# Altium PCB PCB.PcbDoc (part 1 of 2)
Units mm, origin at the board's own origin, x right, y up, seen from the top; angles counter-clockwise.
Board outline 43.18 x 17.78 mm, 4 copper layers (TOP, GND, SIG, BOTTOM), stack 1.586 mm thick; 72 components, 65 nets, 299 pads, 183 vias.
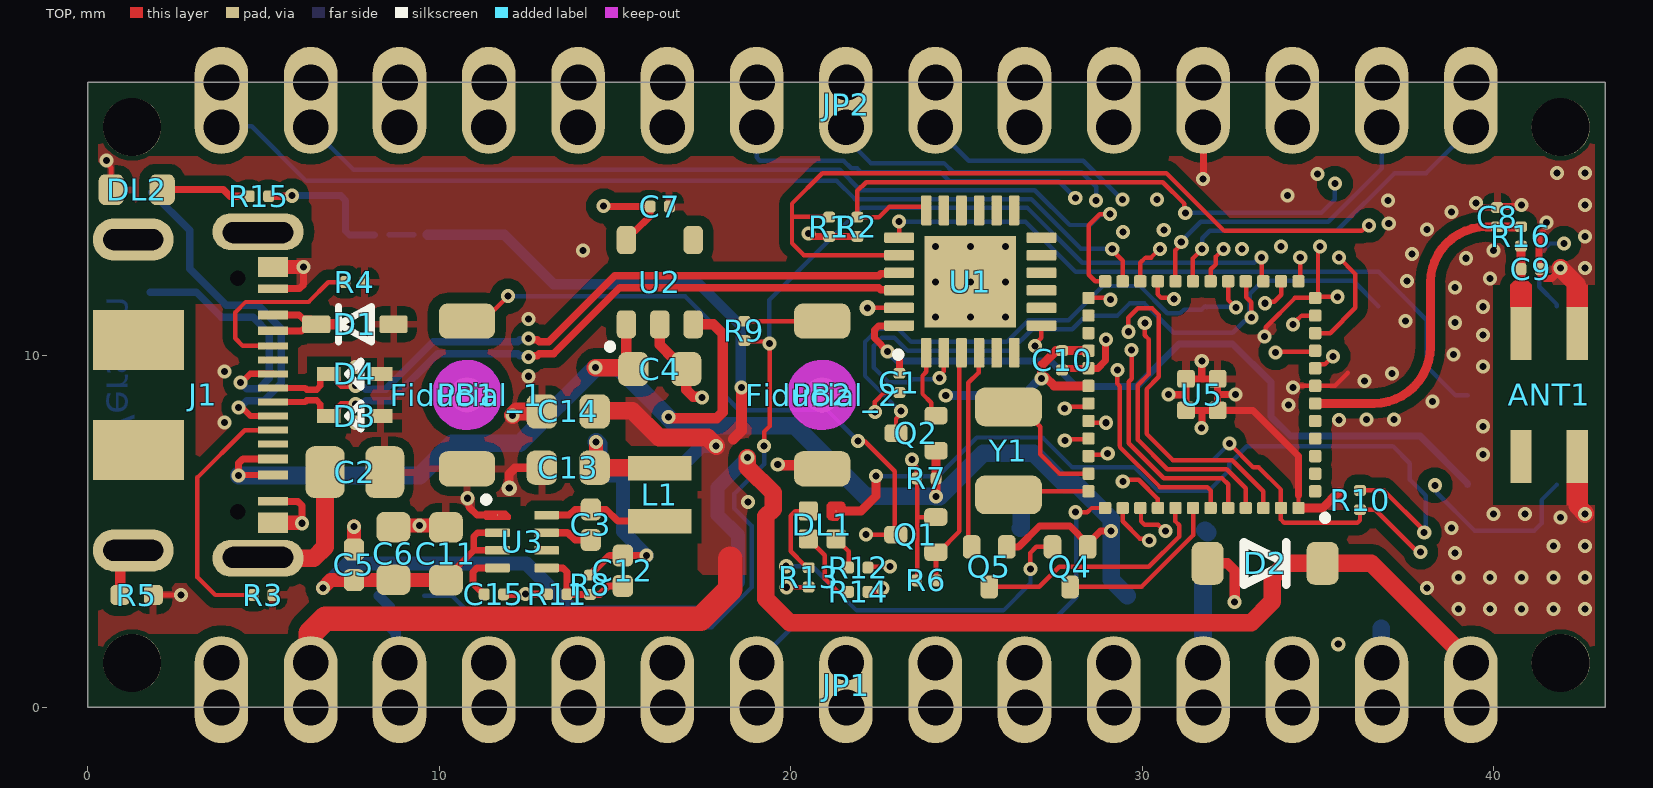
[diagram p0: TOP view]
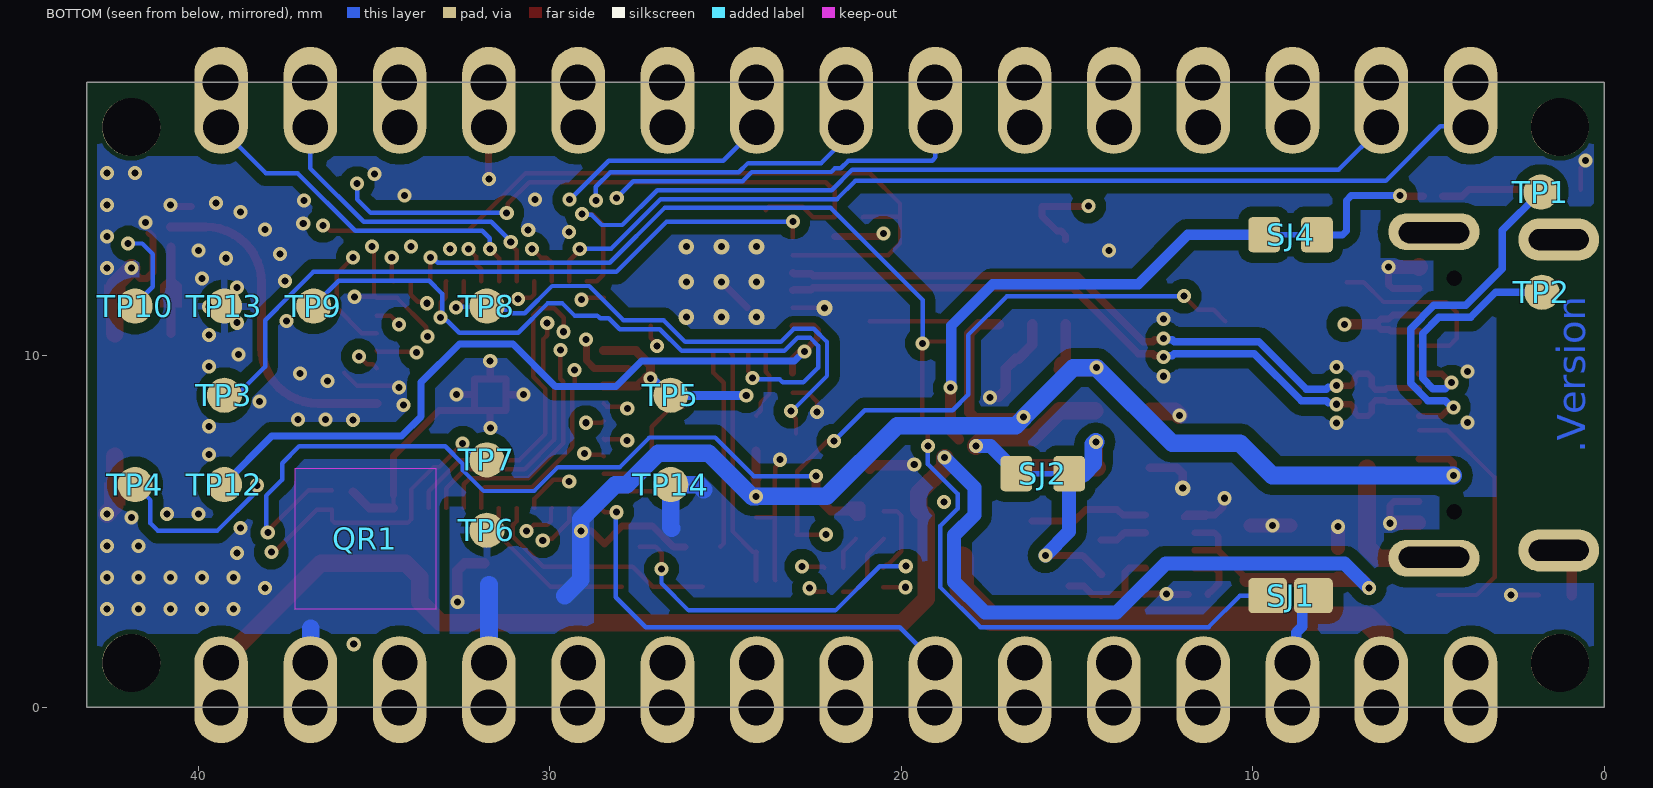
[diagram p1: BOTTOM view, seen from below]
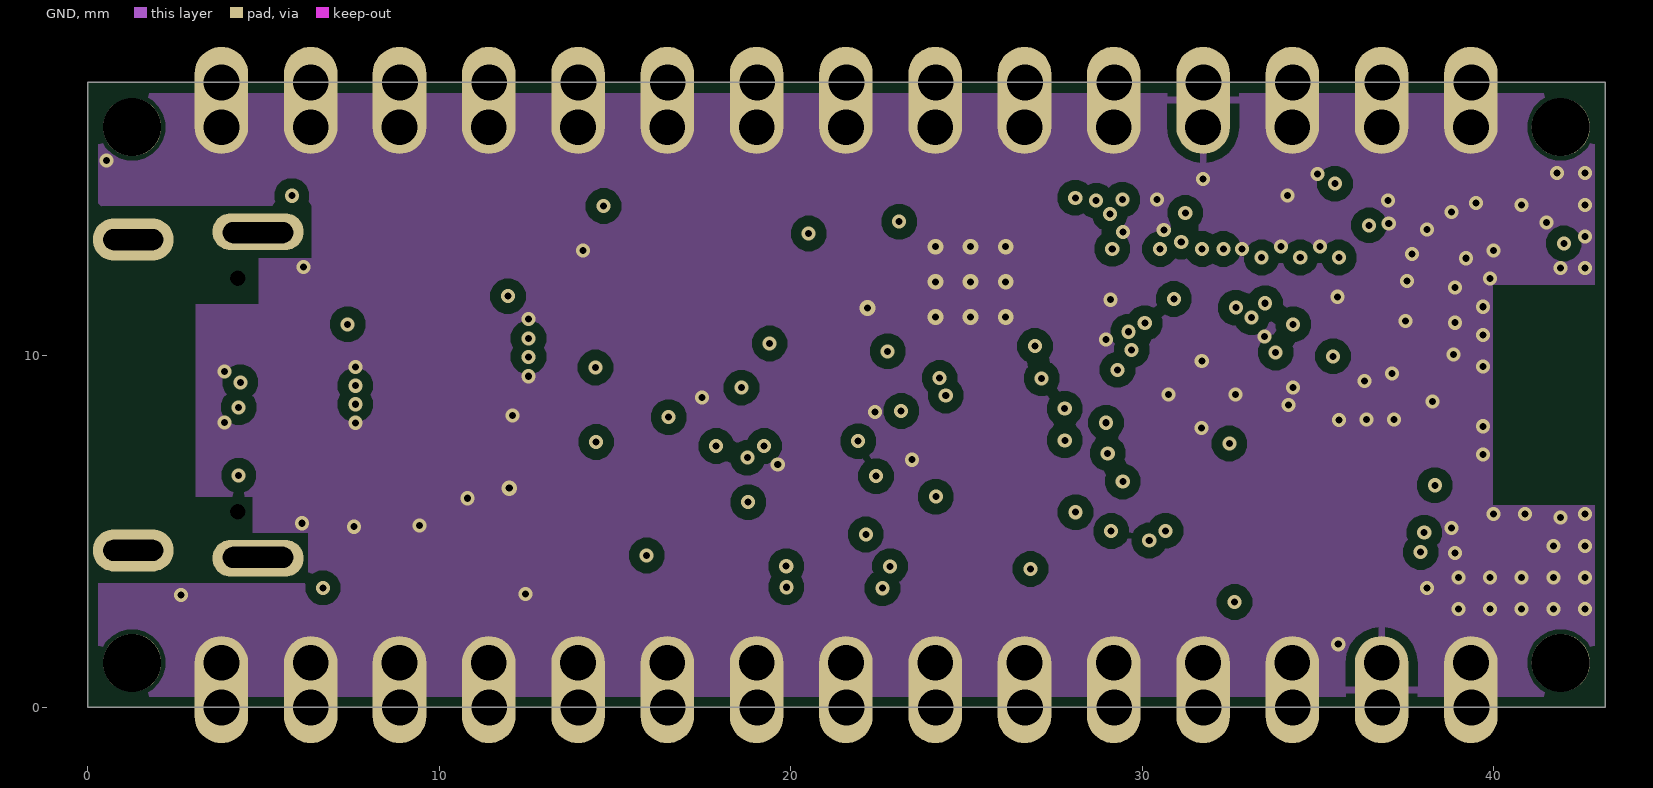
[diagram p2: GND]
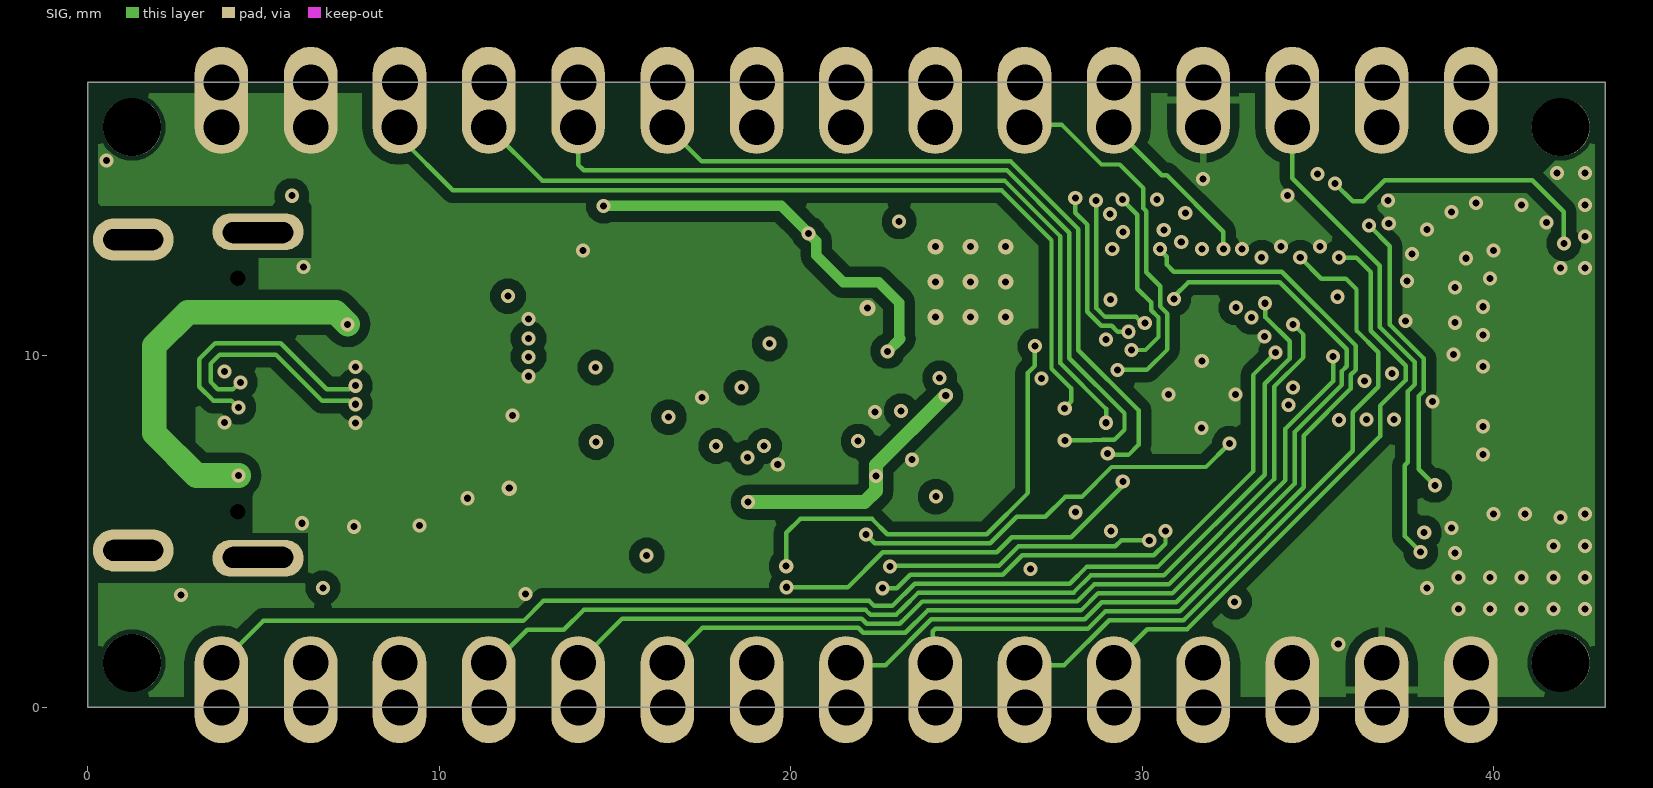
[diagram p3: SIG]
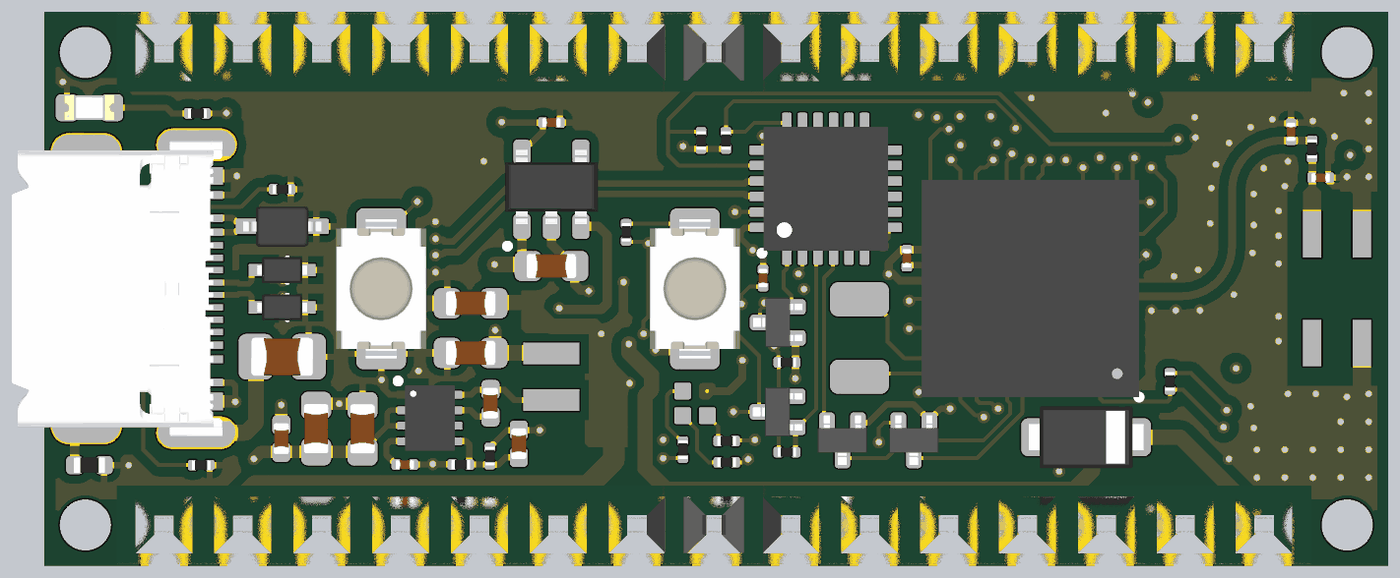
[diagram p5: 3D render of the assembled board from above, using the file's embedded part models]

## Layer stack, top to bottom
Top Solder: solder mask 0.0102, Solder Resist, Dk 3.5
TOP: signal copper 0.018
Dielectric 1: prepreg 0.14, PP-014, Dk 4.2
GND: signal copper 0.035
Dielectric2: core 1.2, FR-4, Dk 4.8
SIG: signal copper 0.035
Dielectric3: prepreg 0.14, PP-014, Dk 4.2
BOTTOM: signal copper 0.018
Bottom Solder: solder mask 0.0102, Solder Resist, Dk 3.5

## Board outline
0,0 0,17.78 43.18,17.78 43.18,0

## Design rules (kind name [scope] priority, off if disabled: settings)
BoardOutlineClearance USBC_outlineclearance [Component = 'J1'] p1: gap=0.1 ignorepadtopadclearanceinfootprint=FALSE
BoardOutlineClearance Castellated_1 [((ObjectKind = 'Pad') And (Component = 'JP1')) OR                                                                                    ((ObjectKind = 'Pad') And (Component = 'JP2'))] p2: gap=0 ignorepadtopadclearanceinfootprint=FALSE
BoardOutlineClearance Silks [(OnLayer('Top Overlay') OR OnLayer('Bottom Overlay'))] p3: gap=0 ignorepadtopadclearanceinfootprint=FALSE
BoardOutlineClearance [All] p4: gap=0.3 ignorepadtopadclearanceinfootprint=FALSE
Clearance SolderJumpers [(ObjectKind = 'Region') And (Net = 'NetR11_2') And (Area = '0.315 sq.') vs (ObjectKind = 'Pad') And (Layer = 'TOP') And (Net = 'VUSB') And (Component = 'SJ4') And (Name = 'SJ4-1')] p1: gap=0 ignorepadtopadclearanceinfootprint=TRUE
Clearance COPPER_0.3mm [All] p2: gap=0.127 ignorepadtopadclearanceinfootprint=TRUE except(0.3: Arc-Fill Arc-Poly Arc-Region Track-Fill Track-Poly Track-Region SMDPad-Fill SMDPad-Poly SMDPad-Region THPad-Fill THPad-Poly THPad-Region Via-Fill Via-Poly Via-Region Fill-Fill Fill-Poly Fill-Region Poly-Poly Poly-Region Region-Region)
Clearance "Generic clearance 0.127mm" [All] p3: gap=0.127 ignorepadtopadclearanceinfootprint=TRUE
ComponentClearance [All] p1: gap=0.2 collisioncheckmode=3 verticalgap=0 showdistances=TRUE
DiffPairsRouting USB [InDifferentialPairClass('USB')] p1: maxlimit=0.254 minlimit=0.127 mostfreqgap=0.254 toplayer_maxgap=0.127 toplayer_prefgap=0.127 toplayer_minwidth=0.18 toplayer_maxwidth=0.213 toplayer_prefwidth=0.213 midlayer2_mingap=0.197 midlayer2_maxgap=0.197 midlayer2_prefgap=0.197 midlayer2_minwidth=0.127 midlayer2_maxwidth=0.127 midlayer2_prefwidth=0.127 bottomlayer_maxgap=0.127 bottomlayer_prefgap=0.127 bottomlayer_minwidth=0.213 bottomlayer_maxwidth=0.213 bottomlayer_prefwidth=0.213 impedanceprofiledriven=TRUE impedanceprofileid={E6B00C31-4C8E-439C-824F-D2B2CDC26F9C} impedanceprofilevalue=90.000000 maxuncoupledlength=12.7
Height [All] p1: minheight=0 maxheight=30 prefheight=12.7
HoleSize [All] p1: absolutevalues=TRUE maxlimit=30 minlimit=0.2 maxpercent=80.000 minpercent=20.000
HoleToHoleClearance [All] p1: gap=0.25 allowstackedmicrovias=FALSE
MinimumAnnularRing castellated [(ObjectKind = 'Pad') And (PadViaLibraryTemplate = 'c70h102m110')] p1: minimumring=0
MinimumAnnularRing [All] p2: minimumring=0.1
NetAntennae NetAntennae_jumpers [(WithinRoom('JUMPERSJ2') OR WithinRoom('JUMPERSJ4'))] p1: netantennaetolerance=2
NetAntennae [All] p2: netantennaetolerance=0
PlaneConnect [All] p1: pad.planeconnectstyle=Relief pad.reliefexpansion=0.508 pad.reliefentries=4 pad.reliefconductorwidth=0.254 pad.reliefairgap=0.254 via.planeconnectstyle=Direct via.reliefexpansion=0.508 via.reliefentries=4 via.reliefconductorwidth=0.254 via.reliefairgap=0.254
PolygonConnect [All] p1: thpad.connectstyle=Relief thpad.reliefconductorwidth=0.2 thpad.reliefentries=4 thpad.polygonreliefangle="90 Angle" thpad.airgapwidth=0.254 smdpad.connectstyle=Relief smdpad.reliefconductorwidth=0.2 smdpad.reliefentries=4 smdpad.polygonreliefangle="90 Angle" smdpad.airgapwidth=0.254 via.connectstyle=Direct via.reliefconductorwidth=0.254 via.reliefentries=4 via.polygonreliefangle="90 Angle" via.airgapwidth=0.254
RoomDefinition JUMPERSJ2 [False vs False] p1: confinementstyle=ConfineIn formatcopy=TRUE lockcomponents=FALSE outline 14.78,7.04 17.18,7.04 17.18,6.264 14.78,6.264
RoomDefinition JUMPERSJ4 [False vs False] p2: confinementstyle=ConfineIn formatcopy=TRUE lockcomponents=FALSE outline 7.788,13.894 10.091,13.894 10.091,12.977 7.788,12.977
RoomDefinition TOP [InComponentClass('TOP')] p3: confinementstyle=ConfineIn formatcopy=TRUE lockcomponents=FALSE outline 44.4,1.5 48.8,1.5 48.8,8.5 44.4,8.5
RoutingVias StandardVias [All] p1: holewidth=0.2 width=0.4 viastyle="Through Hole" minholewidth=0.2 minwidth=0.4 maxholewidth=0.2 maxwidth=0.4
SMDToCorner [All] p1: distance=39370
ShortCircuit short_jumperSJ2 [Component = 'SJ2' vs (InNet('+3V3') OR InNet('NetC12_2'))] p1: allowed=TRUE
ShortCircuit short_jumperSJ4 [Component = 'SJ4' vs (InNet('+3V3') OR InNet('NetR15_2'))] p2: allowed=TRUE
ShortCircuit [All] p3: allowed=FALSE
SilkToSilkClearance [All] p1: silktosilkclearance=0.2
SilkToSolderMaskClearance [IsPad] p1: minsilkscreentomaskgap=0.1 clearancetoexposedcopper=TRUE
SolderMaskExpansion VIAtented [IsVia] p1: expansion=0.102 istentingtop=TRUE
SolderMaskExpansion [All] p2: expansion=0.05 istentingtop=FALSE
SupplyNets "Schematic Supply Nets_4" [InNet('+3V3')] p1: voltage=0.000
SupplyNets "Schematic Supply Nets_3" [InNet('VIN')] p2: voltage=0.000
SupplyNets "Schematic Supply Nets_2" [InNet('GND')] p3: voltage=0.000
SupplyNets "Schematic Supply Nets_1" [InNet('VUSB')] p4: voltage=0.000
SupplyNets "Schematic Supply Nets" [InNet('+3V3_D11')] p5: voltage=0.000
UnConnectedPin [All] p1:
UnRoutedNet [All] p1: checkbadconnections=TRUE
ViasUnderSMD [All] p1: allowed=FALSE
Width [All] p1: maxlimit=1 minlimit=0.127 preferedwidth=0.254 minimp=50.000000 maximp=50.000000 favimp=50.000000
Width StandardTraces [InNetClass('ANT')] p2: maxlimit=5 minlimit=0.127 preferedwidth=0.239 toplayer_minwidth=0.239 toplayer_maxwidth=0.239 bottomlayer_minwidth=0.239 bottomlayer_maxwidth=0.239 impedanceprofiledriven=TRUE impedanceprofileid={62AF9E0A-4658-4788-9E1D-AE6CB9A6C4CD} impedanceprofilevalue=50.000000 minimp=50.000000 maximp=50.000000 favimp=50.000000
19 further rules are at their usual default settings.

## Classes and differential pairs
component class TOP: Fiducial_1 Fiducial_2 QR1
net class ANT: NetANT1_1 NetC8_1
component class U_MGM240S: ANT1 C8 C9 C10 R16 TP7 TP8 TP9 TP14 U5 Y1
differential pair class USB: D
component class U_USB: C2 D1 D3 D4 J1 R3 R4 R5 TP1 TP2
component class "U_SAMD11 USB Bridge": C1 Q1 Q2 Q4 Q5 R1 R2 R6 R7 TP3 TP4 TP10 TP13 U1
component class U_POWER: C3 C4 C5 C6 C7 C11 C12 C13 C14 C15 D2 L1 L? R8 R11 SJ2 TP5 TP12 U2 U3
component class U_INTERFACE: DL1 DL2 JP1 JP2 PB1 PB2 R9 R10 R12 R13 R14 R15 SJ1 SJ4 TP6
differential pair D: +D_P -D_N

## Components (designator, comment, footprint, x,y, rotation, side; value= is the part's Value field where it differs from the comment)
ANT1 "2450AT42E010BE" 2450AT42E0100E 41.58,8.89 r270 top locked
C1 "CL03A104KP3NNNC" CAP-0201 23.097,9.235 r90 top value=100nF
C2 "FV21X472K102ECG" CAP-0805 7.608,6.697 r180 top value=4.7nF
C3 "GRM155R61H104KE19D" CAP-0402 14.318,5.2 r270 top value=100nF
C4 "C1608A106M250NT" CAP-0603 16.28,9.624 r180 top value=10µF
C5 "GRM155R61H104KE19D" CAP-0402 7.58,4.057 r90 top value=100nF
C6 "C1608A106M250NT" CAP-0603 8.7,4.379 r270 top value=10µF
C7 "GRM033R60J105MEA2D" CAP-0201 16.28,14.252 r180 top value=1µF
C8 "CAP-0201-DNP" CAP-0201 40.1,13.95 r90 top
C9 "CAP-0201-DNP" CAP-0201 41.055,12.473 r0 top
C10 "CL03A104KP3NNNC" CAP-0201 27.725,9.875 r90 top value=100nF
C11 "C1608A106M250NT" CAP-0603 10.195,4.373 r270 top value=10µF
C12 "0402N220J500CT" CAP-0402 15.23,3.89 r90 top value=22pF
C13 "C1608A106M250NT" CAP-0603 13.678,6.821 r0 top value=10µF
C14 "C1608A106M250NT" CAP-0603 13.678,8.421 r0 top value=10µF
C15 "GRM033R60J105MEA2D" CAP-0201 11.559,3.22 r180 top value=1µF
D1 "CDSOD323-T05S" "SOD323 CATHODE MARK" 7.608,10.9 r0 top
D2 "PMEG6020AELRX" SOD123-1 33.5,4.1 r180 top
D3 "ESD321DYAR" ESD321DYAR 7.608,8.29 r0 top
D4 "ESD321DYAR" ESD321DYAR 7.608,9.49 r0 top
DL1 "UHD1110-FKA-CL1A13R3Q1BBQFMF3" UHD1110-FKA-CL1A13R3Q1BBQFMF3 20.9,5.194 r270 top
DL2 "HSMG-C190" LEDC1608X80N-AK 1.4,14.73 r0 top locked
Fiducial_1 "Fiducial mark 1mm" "Fiducial mark 1mm-Footprint-1" 10.794,8.89 r90 top
Fiducial_2 "Fiducial mark 1mm" "Fiducial mark 1mm-Footprint-1" 20.9,8.89 r90 top
J1 "CX90B-16P" CX90B-16P-Footprint-1 3.288,8.89 r270 top locked
JP1 "PINHD-1X15-NANO-ANALOG-CASTELLATED" PINHD-1X14_5VF#1 3.81,1.27 r180 top locked
JP2 "PINHD-1X15-NANO-DIGITAL-CASTELLATED" PINHD-1X14_5VF#2 39.37,16.51 r0 top locked
L1 "MAKK2016T3R3M" MAKK2016T3R3M-Footprint-1 16.28,6.052 r90 top value=3.3µH
PB1 "IT-1185AP1C-160G-GTR" C&K_PTS820_NO_HOLES-1 10.794,8.89 r90 top locked
PB2 "IT-1185AP1C-160G-GTR" C&K_PTS820_NO_HOLES-1 20.9,8.89 r90 top locked
Q1 "2N7002T-7-F" SOT523 23.563,4.918 r90 top
Q2 "2N7002T-7-F" SOT523 23.57,7.805 r90 top
Q4 "2N7002T-7-F" SOT523 27.952,4.001 r180 top
Q5 "2N7002T-7-F" SOT523 25.652,4.001 r180 top
QR1 "QR CODE 4x4mm" "QR CODE 4x4mm" 35.25,4.8 r180 bottom locked
R1 "RC0201FR-07100KL" RES-0201 21.1,13.675 r270 top value=100k
R2 "RC0201FR-07100KL" RES-0201 21.9,13.675 r90 top value=100k
R3 "RC0201FR-075K1L" RES-0201 5,3.2 r180 top value=5.1k
R4 "RC0201FR-075K1L" RES-0201 7.608,12.1 r180 top value=5.1k
R5 "CRCW04021M00FKED" RES-0402 1.4,3.2 r180 top value=1M
R6 "RC0201FR-07100KL" RES-0201 23.863,3.618 r180 top value=100k
R7 "RC0201FR-07100KL" RES-0201 23.863,6.518 r180 top value=100k
R8 "RMCF0201FT976K" RES-0201 14.297,3.49 r90 top value=976k
R9 "RC0201FR-075K1L" RES-0201 18.687,10.712 r270 top value=5.1k
R10 "RC0201FR-075K1L" RES-0201 36.2,5.9 r90 top value=5.1k
R11 "AC0201FR-07220KL" RES-0201 13.363,3.221 r0 top value=220k
R12 "CRCW0201499RFKED" RES-0201 21.925,3.98 r0 top value=499
R13 "CRCW0201499RFKED" RES-0201 20.515,3.7 r270 top value=499
R14 "CRCW0201499RFKED" RES-0201 21.925,3.29 r0 top value=499
R15 "CRCW0201499RFKED" RES-0201 4.877,14.544 r0 top value=499
R16 "CRCW02010000Z0ED" RES-0201 40.78,13.4 r270 top value=0
SJ1 "SOLDER JUMPER OPEN 0603" SJ 8.93,3.182 r180 bottom
SJ2 "SOLDER JUMPER CLOSED 0603" "SJ 0603 CLOSED" 15.98,6.652 r180 bottom
SJ4 "SOLDER JUMPER CLOSED 0603" "SJ 0603 CLOSED" 8.93,13.45 r0 bottom
TP1 "Test point 1.00mm" TP-1.00MM 1.81,14.66 r90 bottom
TP2 "Test point 1.00mm" TP-1.00MM 1.778,11.811 r90 bottom
TP3 "Test point 1.00mm" TP-1.00MM 39.263,8.881 r90 bottom locked
TP4 "Test point 1.00mm" TP-1.00MM 41.803,6.341 r90 bottom locked
TP5 "Test point 1.00mm" TP-1.00MM 26.563,8.881 r90 bottom
TP6 "Test point 1.00mm" TP-1.00MM 31.795,5.041 r90 bottom
TP7 "Test point 1.00mm" TP-1.00MM 31.795,7.041 r90 bottom
TP8 "Test point 1.00mm" TP-1.00MM 31.795,11.421 r90 bottom
TP9 "Test point 1.00mm" TP-1.00MM 36.723,11.421 r90 bottom
TP10 "Test point 1.00mm" TP-1.00MM 41.803,11.421 r90 bottom locked
TP12 "Test point 1.00mm" TP-1.00MM 39.263,6.341 r90 bottom locked
TP13 "Test point 1.00mm" TP-1.00MM 39.263,11.421 r90 bottom locked
TP14 "Test point 1.00mm" TP-1.00MM 26.563,6.341 r90 bottom
U1 "ATSAM-D11-D14A-MUT" VQFN24 25.113,12.116 r180 top
U2 "AP2112K-3.3TRG1" SOT25 16.28,12.1 r0 top
U3 "MP2322GQH" QFN50P150X200X90-8L 12.363,4.721 r0 top
U5 "MGM240SD22VNA2R" MGM240SD22VNA 31.7,8.9 r180 top locked
Y1 "CM315D32768DZFT" ABS07 26.2,7.3 r90 top

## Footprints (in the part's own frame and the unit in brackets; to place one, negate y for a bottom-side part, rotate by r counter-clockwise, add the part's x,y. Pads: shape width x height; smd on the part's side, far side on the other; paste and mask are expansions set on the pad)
2450AT42E0100E [mm]
  rect 1.5x0.6 smd: 1(-1.75,-0.8) 2(1.75,-0.8) 3(1.75,0.8) 4(-1.75,0.8)
  TOP region: 2.5,0.5 3.13,0.5 3.13,1.1 2.5,1.1
  TOP region: -2.5,-1.1 -3.13,-1.1 -3.13,-0.5 -2.5,-0.5
  TOP region: -2.5,0.5 -3.13,0.5 -3.13,1.1 -2.5,1.1
  body extent -2.5,-1 2.5,1, height 1.7
ABS07 [mm]
  rrect50% 1.1x1.9 smd: 1(-1.25,0) 2(1.25,0)
  body extent -1.65,-0.83 1.65,0.83, height 0.9
C&K_PTS820_NO_HOLES-1 [mm]
  rrect49% 1x1.6 smd mask+0.05: 1(-2.1,0) 2(2.1,0)
  body extent -2.25,-1.45 2.25,1.45, height 2
CAP-0201 [mm] "Chip Capacitor, 2-Leads, Body 0201 (in) 0603 (mm) IPC Medium Density"
  rrect52% 0.31x0.34 smd mask+0.05: 1(-0.275,0) 2(0.275,0)
  body extent -0.3,-0.15 0.3,0.15, height 0.3
CAP-0402 [mm] "Chip Capacitor, 2-Leads, Body  0402 (in) 1005 (mm), IPC Medium Density"
  rrect52% 0.63x0.58 smd mask+0.05: 1(-0.435,0) 2(0.435,0)
  body extent -0.5,-0.25 0.5,0.25, height 0.5
CAP-0603 [mm] "Chip Capacitor, Body 0603 imperial,1.6x0.8mm, IPC High Density"
  rrect51% 0.87x0.97 smd mask+0.05: 1(-0.75,0) 2(0.75,0)
  body extent -0.8,-0.4 0.8,0.4, height 0.8
CAP-0805 [mm] "Chip Capacitor, Body 0805 imperial, 2.0x1.2mm, IPC Medium Density"
  rrect45% 1.11x1.47 smd mask+0.05: 1(-0.85,0) 2(0.85,0)
  body extent -1,-0.62 1,0.63, height 1.25
CX90B-16P-Footprint-1 [mm]
  rect 0.57x0.85 smd mask+0.05: A1(-3.635,1.988) A12(3.635,1.988)
  rect 0.25x0.85 smd mask+0.05: A4(-2.275,1.988) A9(2.275,1.988) B1(3.025,1.988) B4(1.825,1.988) B9(-1.825,1.988) B12(-3.025,1.988)
  rect 0.2x0.85 smd mask+0.05: A5(-1.4,1.988) A6(-0.6,1.988) A7(0.6,1.988) A8(1.4,1.988) B5(1,1.988) B6(0.2,1.988) B7(-0.2,1.988) B8(-1,1.988)
  round 0.2 hole 0.45 unplated paste-2539.97 mask+0.2: FIXING(-3.32,0.988) FIXING(3.32,0.988)
  rect 1.71x2.6 smd paste-0.3 mask+0.05: FIXING(-1.565,-1.837) FIXING(1.565,-1.837)
  oval 1.05x2.6 hole 0.6 slot 2 at 90 deg copper offset -0.025,0 mask+0.05: SHIELD1(-4.62,1.563)
  oval 1.05x2.6 hole 0.6 slot 2 at 90 deg copper offset 0.025,0 mask+0.05: SHIELD2(4.62,1.563)
  oval 1.2x2.3 hole 0.6 slot 1.7 at 90 deg mask+0.05: SHIELD3(-4.42,-1.987) SHIELD4(4.42,-1.987)
  body extent -4.77,-4.4 4.77,2.4, height 3.17
ESD321DYAR [mm] "ESD321DYAR SOD-523 1.6x0.8mm"
  rect 0.67x0.4 smd mask+0.05: 1(0.74,0) 2(-0.74,0)
  silkscreen extent -0.2,-0.37 0.17,0.37, body extent -0.8,-0.43 0.8,0.43, height 0.82
"Fiducial mark 1mm-Footprint-1" [mm]
  round 1 smd paste-10 mask+0.5: 1(0,0)
  TOP keep-out circle w1: c0,0 r0.5
LEDC1608X80N-AK [mm]
  rrect50% 0.72x0.87 smd: A(0.725,0) C(-0.725,0)
  body extent -0.8,-0.4 0.8,0.4, height 0.79
MAKK2016T3R3M-Footprint-1 [mm]
  rect 0.7x1.8 smd mask+0.05: 1(-0.75,0) 2(0.75,0)
  body extent -1,-0.8 1,0.8, height 1
MGM240SD22VNA [mm]
  rrect30% 0.35x0.35 smd mask+0.05: 1(-3.225,2.75) 2(-3.225,2.25) 3(-3.225,1.75) 4(-3.225,1.25) 5(-3.225,0.75) 6(-3.225,0.25) 7(-3.225,-0.25) 8(-3.225,-0.75) 9(-3.225,-1.25) 10(-3.225,-1.75) 11(-3.225,-2.25) 12(-3.225,-2.75) 13(-2.75,-3.225) 14(-2.25,-3.225) 15(-1.75,-3.225) 16(-1.25,-3.225) 17(-0.75,-3.225) 18(-0.25,-3.225) 19(0.25,-3.225) 20(0.75,-3.225) 21(1.25,-3.225) 22(1.75,-3.225) 23(2.25,-3.225) 24(2.75,-3.225) 25(3.225,-2.75) 26(3.225,-2.25) 27(3.225,-1.75) 28(3.225,-1.25) 29(3.225,-0.75) 30(3.225,-0.25) 31(3.225,0.25) 32(3.225,0.75) 33(3.225,1.25) 34(3.225,1.75) 35(3.225,2.25) 36(3.225,2.75) 37(2.75,3.225) 38(2.25,3.225) 39(1.75,3.225) 40(1.25,3.225) 41(0.75,3.225) 42(0.25,3.225) 43(-0.25,3.225) 44(-0.75,3.225) 45(-1.25,3.225) 46(-1.75,3.225) 47(-2.25,3.225) 48(-2.75,3.225)
  rrect30% 0.5x0.5 smd mask+0.05: 49(-0.45,0.45) 50(0.45,0.45) 51(0.45,-0.45) 52(-0.45,-0.45)
  silkscreen extent -3.55,3.46 -3.46,3.55, body extent -3.5,-3.5 3.5,3.5, height 1.27
PINHD-1X14_5VF#1 [mil]
  oval 60x120 hole 40 copper offset 0,30 paste-99999: 1(0,0) 2(-100,0) 3(-199.41,0) 4(-299.41,0) 5(-399.41,0) 6(-499.41,0) 7(-599.41,0) 8(-699.41,0) 9(-799.41,0) 10(-899.41,0) 11(-999.41,0) 12(-1099.41,0) 13(-1199.41,0) 14(-1299.41,0) 15(-1399.41,0)
  round 27.56 hole 40 mask+7.87: 1(0,50) 2(-100,50) 3(-200,50) 4(-300,50) 5(-400,50) 6(-500,50) 7(-600,50) 8(-700,50) 9(-800,50) 10(-900,50) 11(-1000,50) 12(-1100,50) 13(-1200,50) 14(-1300,50) 15(-1400,50)
  body extent -1454,-50 60,50, height 335
PINHD-1X14_5VF#2 [mil]
  oval 60x120 hole 40 copper offset 0,30 paste-99999: 1(-0.59,0) 2(-100.59,0) 3(-200.59,0) 4(-300.59,0) 5(-400.59,0) 6(-500.59,0) 7(-600.59,0) 8(-700.59,0) 9(-800.59,0) 10(-900.59,0) 11(-1000.59,0) 12(-1100.59,0) 13(-1200.59,0) 14(-1300,0) 15(-1400,0)
  round 27.56 hole 40 mask+7.87: 1(0,50) 2(-100,50) 3(-200,50) 4(-300,50) 5(-400,50) 6(-500,50) 7(-600,50) 8(-700,50) 9(-800,50) 10(-900,50) 11(-1000,50) 12(-1100,50) 13(-1200,50) 14(-1300,50) 15(-1400,50)
  body extent -1460,-50 54,50, height 335
QFN50P150X200X90-8L [mm] "QFN, 8-Leads, Body 1,50x2,00mm, Pitch 0,50mm, IPC High Density"
  round 0.025 smd mask+0.05: 1(-0.7,0.75)
  rrect25% 0.7x0.25 smd mask+0.05: 2(-0.7,0.25) 3(-0.7,-0.25) 4(-0.7,-0.75) 5(0.7,-0.75) 6(0.7,-0.25) 7(0.7,0.25) 8(0.7,0.75)
  TOP region: -1.044,0.625 -1.056,0.627 -1.066,0.634 -1.073,0.644 -1.075,0.656 -1.075,0.656 -1.075,0.844 -1.073,0.856 -1.066,0.866 -1.056,0.873 -1.044,0.875 -1.044,0.875 -0.452,0.875 -0.325,0.748 -0.325,0.656 -0.327,0.644 -0.334,0.634 -0.344,0.627 -0.356,0.625 -0.356,0.625
  silkscreen extent -1.07,1.14 -0.97,1.24, body extent -0.8,-1.05 0.8,1.05, height 0.9
"QR CODE 4x4mm" [mm]
  TOP keep-out region: -2,2 2,2 2,-2 -2,-2
RES-0201 [mm] "Chip Resistor, 2-Leads, Body 0201 (in) 0603 (mm) IPC Medium Density"
  rrect52% 0.31x0.34 smd mask+0.05: 1(-0.275,0) 2(0.275,0)
  body extent -0.3,-0.15 0.3,0.15, height 0.24
RES-0402 [mm] "Chip Resistor, 2-Leads, Body  0402 (in) 1005 (mm), IPC Medium Density"
  rrect51% 0.55x0.58 smd mask+0.05: 1(-0.475,0) 2(0.475,0)
  body extent -0.5,-0.25 0.5,0.25, height 0.34
SJ [mm]
  rrect25% 1.1x1 smd paste-2539.97 mask+0.1: 1(0.65,0) 2(-0.65,0)
"SJ 0603 CLOSED" [mm]
  rrect25% 0.9x1 smd paste-2539.97 mask+0.1: 1(0.75,0) 2(-0.75,0)
  TOP lines w0.15: 0.35,0 -0.35,0
SOD123-1 [mm]
  rrect50% 0.91x1.22 smd: A(1.635,0) C(-1.635,0)
  silkscreen extent -0.6,-0.6 0.6,0.6, body extent -1.85,-1 1.85,1, height 1.2
"SOD323 CATHODE MARK" [mm]
  rrect25% 0.8x0.5 smd mask+0.05: 1(-1.1,0) 2(1.1,0)
  silkscreen extent -0.47,-0.5 0.47,0.5, body extent -1.26,-0.65 1.26,0.65, height 1.14
SOT25 [mil]
  rrect50% 21.65x31.5 smd mask+1.97: 1(-37.4,-47.24) 2(0,-47.24) 3(37.4,-47.24) 4(37.4,47.24) 5(-37.4,47.24)
  silkscreen extent -58,-74 -54,-70, body extent -59,-44 59,50, height 43
SOT523 [mm]
  rrect50% 0.5x0.66 smd: D(0,0.57) G(-0.5,-0.57) S(0.5,-0.57)
  body extent -0.8,-0.8 0.8,0.8, height 0.8
TP-1.00MM [mm]
  rrect100% 1x1 smd paste-2.54: X(0,0)
UHD1110-FKA-CL1A13R3Q1BBQFMF3 [mm]
  rrect25% 0.54x0.54 smd mask+0.05: 1(-0.395,-0.395) 2(0.395,-0.395) 3(0.395,0.395)
  round 0.025 smd mask+0.05: 4(-0.395,0.395)
  TOP region: -0.35,0.665 -0.125,0.44 -0.125,0.265 -0.136,0.212 -0.166,0.166 -0.212,0.136 -0.265,0.125 -0.265,0.125 -0.525,0.125 -0.578,0.136 -0.624,0.166 -0.654,0.212 -0.665,0.265 -0.665,0.265 -0.665,0.525 -0.654,0.578 -0.624,0.624 -0.578,0.654 -0.525,0.665 -0.525,0.665
  body extent -0.5,-0.5 0.5,0.5, height 0.63
VQFN24 [mm]
  rrect25% 0.3x0.85 smd mask+0.05: 1(1.25,2.025) 2(0.75,2.025) 3(0.25,2.025) 4(-0.25,2.025) 5(-0.75,2.025) 6(-1.25,2.025) 13(-1.25,-2.025) 14(-0.75,-2.025) 15(-0.25,-2.025) 16(0.25,-2.025) 17(0.75,-2.025) 18(1.25,-2.025)
  rrect25% 0.85x0.3 smd mask+0.05: 7(-2.025,1.25) 8(-2.025,0.75) 9(-2.025,0.25) 10(-2.025,-0.25) 11(-2.025,-0.75) 12(-2.025,-1.25) 19(2.025,-1.25) 20(2.025,-0.75) 21(2.025,-0.25) 22(2.025,0.25) 23(2.025,0.75) 24(2.025,1.25)
  rect 2.6x2.6 smd paste-5 mask+0.05: EXP(0,0)
  silkscreen extent 2,2.03 2.1,2.13, body extent -2,-2 2,2, height 0.9

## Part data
ANT1: library part Y0004-A.2, "ANTENNA CHIP 2.4GHZ", Frequency=2.4GHz, Manufacturer=Johanson, Max Frequency=2.48GHz, Max Power Dissipation=2W
C1 C10: library part C0113-A.6, "CAP CHIP 0201 100nF 10% 10V X5R", Case Code (Imperial)=0201, Dielectric=X5R, Manufacturer="Samsung Electro-Mechanics", Tolerance=10%, Voltage=10V
C2: library part C0059-A.14, "CAP CHIP 0805 4.7nF 10% 1000V X7R", Case Code (Imperial)=0805, Dielectric=X7R, Manufacturer="PSA Shenzen", Manufacturer 2=KEMET, Part number 2=C0805V472KDRACTU, Part number 3=C0805C472KDRACTU, Tolerance=10%, Voltage=1kV
C3 C5: library part C0015-A.14, "CAP CHIP 0402 100nF 10% 50V X5R", Case Code (Imperial)=0402, Dielectric=X5R, Manufacturer=Murata, Tolerance=10%, Voltage=50V
C4 C6 C11 C13 C14: library part C0047-A.18, "CAP CHIP 0603 10uF 20% 25V X5R", Case Code (Imperial)=0603, Dielectric=X5R, Manufacturer=Hottech, Manufacturer 2="Murata Electronics", Part number 2=CL10A106MA8NRNC, Tolerance=20%, Voltage=25V
C7 C15: library part C0002-A.15, "CAP CHIP 0201 1uF 20% 6.3V X5R", Case Code (Imperial)=0201, Dielectric=X5R, Manufacturer=Murata, Tolerance=20%, Voltage=6.3V
C8 C9: library part UT0015-A.7, "DNP CAP CHIP 0201"
C12: library part C0029-A.14, "CAP CHIP 0402 22pF 5% 50V C0G", Case Code (Imperial)=0402, Dielectric=C0G, Manufacturer=Walsin, Manufacturer 2="Murata Electronics", Manufacturer 3=KEMET, Part number 2=GRM1555C1H220JA01D, Part number 3=C0402C220K5GAC7867, Tolerance=5%, Voltage=50V
D1: library part D0081-A.1, "DIODE TVS Vr 5V, Vbr min 6V, 500W, SOD323", Manufacturer=Bourns
D2: library part D0026-A.6, "DIODE SCHOTTKY SMD 2A 60V SOD123FL", Forward Current=2A, Forward Voltage=0.6V, Manucturer Part Number 2=SS26L, Manufacturer=Nexperia
D3 D4: library part P0022-4, "TVS 1CH, 30kV, USB 2.0 ETH 10/100/1000, 0-3.6V, 0.9pF, IEC61000-4-5 peak current 80A surge 40W 6A, DC breakdown min 4.5V, SOD523 1.6x0.8mm", Manufacturer="Texas Instruments"
DL1: library part L0026-A.4, "LED RGB BLACK BODY SMD", Manufacturer="Cree LED"
DL2: library part L0009-A.5, "LED SMD 0603 GREEN/568 15mcd 120^", Manufacturer=Broadcom
Fiducial_1 Fiducial_2: library part UT0023-A.7, "Fiducial mark 1mm clearance 2mm"
J1: library part J0272-A.3, "CONN RCPT USB3.1 TYPEC 16POS SMD", Manufacturer=Hirose
JP1: library part J0158-A.4, "CONN THD SOCKET F/1/D 15V JANALOG NANO-TYPE CASTELLATED"
JP2: library part J0183-A.4, "CONN THD SOCKET F/1/D 15V JDIGITAL NANO-TYPE CASTELLATED"
L1: library part I0045-A.10, "IND CHIP 0806 3.3 uH 20% 1.2A", Case Code (Imperial)=0806, Case Code (Metric)=2016, Current Rating=1.2A, DC Resistance (DCR)=255mR, Inductance=3.3µH, Manufacturer="Taiyo Yuden", Manufacturer 2=Murata, Manufacturer Part Number 2=LQM2MPN3R3NG0L, Max DC Current=1.15A, Max Operating Temperature=105°C, Min Operating Temperature=-40°C, Package Quantity=3000, Resistor Type=Wirewound, Test Frequency=2MHz, Tolerance=20%
PB1 PB2: library part B0001-A.7, "PUSHBUTTON WHITE NO ANCHORS", Color=White, Manufacturer=Switronic
Q1 Q2 Q4 Q5: library part T0003-A.2, "MOSFET N-CH 60V 115mA SOT523", Manufacturer="Diodes Inc."
QR1: library part QR-0001-A.2, "QR CODE 4x4mm on layer 34 (This is not a component)", Manufacturer="This is not a component"
R1 R2 R6 R7: library part R0146-A.21, "RES CHIP 0201 100k 1% 1/20W", Case Code (Imperial)=0201, Manufacturer=Yageo, Manufacturer 2="Samsung Electro-Mechanics", Power=50mW, Temperature coefficient=200ppm, Tolerance=1%
R3 R4 R9 R10: library part R0169-A.24, "RES CHIP 0201 5.1k 1% 1/20W", Case Code (Imperial)=0201, Manufacturer=Yageo, Power=50mW, Temperature coefficient=200ppm, Tolerance=1%
R5: library part R0058-A.24, "RES CHIP 0402 1M 1% 1/16W", Case Code (Imperial)=0402, Manufacturer=Vishay, Power=62.5mW, Temperature coefficient=100ppm, Tolerance=1%
R8: library part R0198-A.20, "RES CHIP 0201 976k 1% 1/20W", Case Code (Imperial)=0201, Manufacturer="Stackpole Electronics", Power=50mW, Temperature coefficient=200ppm, Tolerance=1%
R11: library part R0199-A.20, "RES CHIP 0201 220k 1% 1/20W", Case Code (Imperial)=0201, Manufacturer=Yageo, Power=50mW, Temperature coefficient=200ppm, Tolerance=1%
R12 R13 R14 R15: library part R0185-A.22, "RES CHIP 0201 499R 1% 1/20W", Case Code (Imperial)=0201, Manufacturer=Vishay, Power=50mW, Temperature coefficient=100ppm, Tolerance=1%
R16: library part R0140-A.21, "RES CHIP 0201 0R", Case Code (Imperial)=0201, Manufacturer=Vishay, Power=50mW, Temperature coefficient=0ppm, Tolerance=0%
SJ1: library part UT0038-A.4
SJ2 SJ4: library part UT0039-A.3
TP1 TP2 TP3 TP4 TP5 TP6 TP7 TP8 TP9 TP10 TP12 TP13 TP14: library part UT0013-A.6, Manufacturer="This is not a component"
U1: library part U0040-A.9, "IC uC Cortex M0, 16KB flash, 4KB SRAM, 48MHz, USB, 3x SERCOM, RTC, 12PWM, ADC 12b, DAC 10b, VDD 1.6V to 3.6V, QFN24 4x4mm", Manufacturer=Microchip
U2: library part U0027-A.11, "IC LDO Vin max 6.5V Vout 3V3 Iout 600mA +EN  SOT25", Manufacturer="Diodes Inc"
U3: library part U0072-A.8, "IC STEP DOWN CONV 1A 22V QFN8", Manufacturer="Monolithic Power Systems"
U5: library part U0354-A.5, "802.15.4, Bluetooth Bluetooth v5.3, Thread, Zigbee® Transceiver Module 2.4GHz PCB Trace, Antenna Not Included, U.FL Surface Mount", Manufacturer="Silicon Labs"
Y1: library part X0003-A.5, "CRYSTAL 32.768kHz 20ppm 12.5pF SMD 1.6x0.9mm", Frequency=32.768kHz, Frequency Stability=0.12%, Frequency Tolerance=20ppm, Load Capacitance=12.5pF, Manufacturer="Citizen FineDevice", Max Operating Temperature=85°C, Min Operating Temperature=-40°C, Series Resistance=70kR

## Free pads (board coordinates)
  round 1.651 hole 1.651 unplated: MH(1.27,1.27) MH(1.27,16.51) MH(41.91,1.27) MH(41.91,16.51)

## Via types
v1: diameter 0.4, hole 0.2, TOP to BOTTOM, tented both sides, 172 vias
v2: diameter 0.45, hole 0.2, TOP to BOTTOM, tented both sides, 11 vias

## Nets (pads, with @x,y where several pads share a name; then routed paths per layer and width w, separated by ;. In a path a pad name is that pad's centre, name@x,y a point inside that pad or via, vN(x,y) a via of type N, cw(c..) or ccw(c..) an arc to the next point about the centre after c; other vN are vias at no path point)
+3V3: C10.2 C14.2 DL1.4 JP1.2 R10.2 SJ2.2 SJ4.1 TP5.X U5.28 U5.30 | length 69.7
  TOP w0.127: R10.2@36.2,6.175 36.878,6.175 38.027,5.026 v1(38.027,4.974)
  TOP w0.254: DL1.4@21.295,5.589 22.003,5.589 22.433,6.019 v1(22.433,6.58) ; v1(27.145,9.363) 27.145,9.739 27.556,10.15 C10.2@27.725,10.15 U5.28@28.475,10.15 ; v1@27.247,9.402 27.499,9.15 U5.30@28.475,9.15
  TOP w0.3: 18.364,7.635 18.605,7.876 v1(18.605,9.101)
  TOP w0.5: C14.2@14.504,8.445 15.5,8.445 16.264,7.681 17.64,7.681 v1(17.883,7.438)
  TOP w0.7: JP1.2@6.35,1.27 6.35,2.115 6.76,2.525 17.447,2.525 18.284,3.362 18.284,4.236
  SIG w0.4: v1(18.794,5.841) 22.108,5.841 22.433,6.166 v1(22.433,6.58) 22.433,6.895 v1(24.415,8.877)
  BOTTOM w0.127: v1@22.437,6.577 24.196,6.577 25.3,7.68 27.169,7.68 28.009,6.84 29.769,6.84 30.451,6.158 31.889,6.158 32.486,6.755 32.486,6.933 32.98,7.428 37.136,7.428 37.614,6.951 37.614,6.484 38.069,6.029 38.069,5.016 v1(38.027,4.974)
  BOTTOM w0.254: v1(24.415,8.877) 25.349,8.877 25.352,8.879 26.684,8.879 26.684,8.942 27.105,9.363 v1(27.145,9.363)
  BOTTOM w0.3: SJ4.1@9.68,13.45 11.854,13.45 13.263,12.041 17.408,12.041 18.585,10.863 18.585,9.12 v1(18.605,9.101)
  BOTTOM w0.4: SJ2.2@16.739,6.71 17.467,7.438 v1(17.883,7.438)
+3V3_D11: C1.2 C7.2 R1.2 R2.1 TP12.X U1.24 U2.5 | length 37.4
  TOP w0.2: v1(14.68,14.265) 14.694,14.252 C7.2@16.005,14.252 16.005,13.975 15.58,13.55 15.455,13.55 15.33,13.425 U2.5@15.33,13.3 ; v1(20.517,13.483) 20.6,13.4 R1.2@21.1,13.4 R2.1@21.9,13.4 ; U1.24@23.079,10.857 22.5,10.857 22.383,10.74 22.383,10.511 22.791,10.104 22.909,10.104 23.102,9.911 C1.2@23.102,9.515
  SIG w0.3: v1@14.683,14.268 19.74,14.268 20.3,13.708 20.3,13.7 v1(20.517,13.483) 20.734,13.266 20.734,12.866 21.5,12.1 22.504,12.1 23.088,11.516 23.088,10.509 23.114,10.484 v1(22.762,10.132)
  BOTTOM w0.2: v1(22.762,10.132) 23.039,9.855 27.398,9.855 28.118,9.136 29.847,9.136 31.053,10.341 32.575,10.341 33.664,9.252 33.664,8.272 34.218,7.718 37.914,7.718 39.263,6.37 TP12.X@39.263,6.341
A0: JP1.4 U5.14 | length 30.8
  TOP w0.127: v1(33.5,11.5) 33.541,11.541 33.757,11.541 33.956,11.739 U5.14@33.956,12.119
  SIG w0.127: JP1.4@11.415,1.27 11.567,1.27 12.507,2.209 13.547,2.209 14.114,2.776 22.134,2.776 22.276,2.634 23.003,2.634 23.178,2.809 23.638,3.27 28.051,3.27 28.537,3.755 30.621,3.755 33.487,6.622 33.487,9.214 34.2,9.926 34.2,10.415 33.508,11.107 v1@33.508,11.492
A1: JP1.5 U5.11 | length 27.6
  TOP w0.127: v1@34.3,11 34.387,11 34.537,11.15 U5.11@34.925,11.15
  SIG w0.127: JP1.5@13.955,1.27 15.207,2.522 22.029,2.522 22.171,2.38 23.108,2.38 23.283,2.555 23.743,3.016 28.157,3.016 28.643,3.501 30.759,3.501 33.755,6.498 33.755,9.122 34.592,9.959 34.592,10.608 v1(34.3,10.9)
A2: JP1.6 U5.8 | length 24.6
  TOP w0.127: U5.8@34.925,9.65 35.036,9.762 35.203,9.762 v1(35.433,9.991)
  SIG w0.127: JP1.6@16.495,1.27 17.493,2.268 21.924,2.268 22.066,2.126 23.265,2.126 23.9,2.762 28.262,2.762 28.748,3.247 30.864,3.247 34.079,6.463 34.079,7.929 35.433,9.283 v1(35.433,9.991)
A3: JP1.7 U5.37 | length 13.2
  TOP w0.127: v1(28.108,5.555) 28.441,5.555 28.562,5.675 U5.37@28.95,5.675
  BOTTOM w0.127: JP1.7@19.035,1.27 20.048,2.283 27.276,2.283 28.126,3.133 28.126,5.537 v1(28.108,5.555)
A4: JP1.8 U5.21 | length 26.2
  TOP w0.127: U5.21@30.45,12.125 30.45,11.75 30.541,11.659 30.869,11.659 v1(30.905,11.623)
  SIG w0.127: JP1.8@21.575,1.27 21.639,1.206 22.704,1.206 24.005,2.508 28.367,2.508 28.853,2.993 30.969,2.993 34.346,6.371 34.346,7.837 35.687,9.178 35.687,9.572 35.823,9.709 35.823,10.191 33.914,12.1 31.318,12.1 30.905,11.687 v1(30.905,11.623)
A5: JP1.9 U5.22 | length 25.9
  TOP w0.127: U5.22@29.95,12.125 29.95,12.65 30.1,12.8 30.256,12.8 30.5,13.044 v1(30.511,13.044)
  SIG w0.127: JP1.9@24.047,1.27 24.047,2.167 24.121,2.242 28.461,2.242 28.958,2.739 31.074,2.739 34.6,6.265 34.6,7.732 35.941,9.072 35.941,9.467 36.077,9.604 36.077,10.297 33.974,12.4 30.9,12.4 30.699,12.601 30.699,12.819 30.511,13.007 v1(30.511,13.044)
A6: JP1.10 U5.13 | length 19.6
  TOP w0.127: U5.13@34.45,12.125 34.5,12.175 v1@34.5,12.7
  SIG w0.127: JP1.10@26.655,1.27 26.719,1.206 27.784,1.206 29.063,2.485 31.18,2.485 35.995,7.301 35.995,8.395 36.722,9.122 36.722,9.451 36.72,9.453 36.72,10.104 36.1,10.724 36.1,11.9 35.8,12.2 35.1,12.2 v1(34.5,12.8)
